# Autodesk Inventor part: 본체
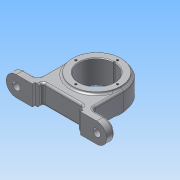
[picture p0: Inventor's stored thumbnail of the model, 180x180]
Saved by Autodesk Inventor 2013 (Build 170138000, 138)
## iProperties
Created: 2019-05
Part Number: 본체
Material: 알루미늄 6061
Document SubType Name: Modeling
Designer: Gpr
Density: 2.71 g/cm^3
Mass: 456.571 g
Surface Area: 322.88 cm^2
Volume: 168.476 cm^3
Author: Gpr
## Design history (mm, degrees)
sketch "스케치1"
  geometry: L1 (-30, 0)-(-30, -6); L2 (-30, -6)-(-36, -6); L3 (-36, -6)-(-36, -10); L4 (-36, -10)-(-75, -10); L5 (-75, -10)-(-75, 2); L6 (-30, 0)-(0, 0); L7 (0, 10.162)-(0, 0); L8 (30, -6)-(36, -6); L9 (30, 0)-(30, -6); L10 (30, 0)-(0, 0); L11 (75, -10)-(75, 2); L12 (36, -10)-(75, -10); L13 (36, -6)-(36, -10); L14 (-40, 50)-(-40, 2); L15 (40, 50)-(40, 2); L16 (-75, 2)-(-40, 2); L17 (40, 2)-(75, 2); L18 (-40, 50)-(40, 50); A1 r 40 centre (0, 50) between (-40, 50) and (40, 50); 2 further points
  constraints: 36 end point, 8 symmetric about line, 5 horizontal, 5 vertical, 3 coincident, 2 point on circle, 1 centre point, 1 point on line, 1 tangent, 1 vertical alignment
  dimensions: "d4" = 10 distance between parallel lines of L6 L4; "d6" = 30 distance from line of point (0, 0) L1; "d7" = 4 distance between parallel lines of L4 L2; "d8" = 75 distance from line of point (0, 0) L5; "d9" = 72 distance between parallel lines of L13 L3; "d11" = 80 diameter of A1; "d12" = 60 distance from line of L4 A1.centre; "d13" = 12 distance between parallel lines of L4 L16
extrude "돌출1" new body sketch "스케치1" stored distance "d14" = 30; taper "d15" = 0 deg
sketch "스케치2"
  geometry: L1 (-30, 0)-(-30, -6) reference; L2 (-30, -6)-(-36, -6) reference; L3 (-36, -6)-(-36, -10) reference; L4 (-36, -10)-(-75, -10) reference; L5 (-75, -10)-(-75, 2) reference; L6 (-75, 2)-(-40, 2) reference; L7 (-40, 2)-(-40, 50) reference; L8 (40, 50)-(40, 2) reference; L9 (40, 2)-(75, 2) reference; L10 (75, 2)-(75, -10) reference; L11 (75, -10)-(36, -10) reference; L12 (36, -10)-(36, -6) reference; L13 (36, -6)-(30, -6) reference; L14 (30, -6)-(30, 0) reference; L15 (30, 0)-(-30, 0) reference; C1 r 36 at (0, 50); A1 r 40 centre (0, 50) between (40, 50) and (-40, 50) reference; 1 further point
  constraints: 1 centre point, 1 coincident
  dimensions: "d16" = 72 diameter of C1
extrude "돌출2" join sketch "스케치2" stored distance "d17" = 36; taper "d18" = 0 deg
sketch "스케치3"
  geometry: C1 r 36 at (0, 0) reference; C2 r 26 at (0, 0); 1 further point
  constraints: 1 centre point, 1 coincident
  dimensions: "d19" = 52 diameter of C2
extrude "돌출3" cut sketch "스케치3" stored distance "d21" = 36; taper "d22" = 0 deg
sketch "스케치4" dims "d23" = 62
  geometry: C1 r 26 at (0, 0) reference; C2 r 36 at (0, 0) reference; 3 further points
  constraints: 2 vertical alignment, 1 coincident, 2 other
hole "구멍1" sketch "스케치4" at (0, 31) diameter "d24" = 3.242; stored, may be unused: countersink angle "d28" = 90 deg, drill point angle "d30" = 118 deg; dims "d25" = 6, "d26" = 4, "d27" = 2, "d29" = 8
sketch "스케치5"
  geometry: L1 (0, 0)-(39, 0) reference; L2 (111, 0)-(150, 0) reference; C1 r 9 at (15, 15); C2 r 9 at (135, 15); 1 further point
  constraints: 2 centre point
  dimensions: "d34" = 18 diameter of C1; "d36" = 60 distance of point (75, 15) C1.centre; "d37" = 18 diameter of C2; "d38" = 60 distance of C2.centre point (75, 15); "d39" = 15 distance from line of L1 C1.centre; "d40" = 15 distance from line of C2.centre L2
extrude "돌출4" join sketch "스케치5" distance "d41" = 3; taper "d42" = 0 deg
sketch "스케치6"
  geometry: L1 (20, 15)-(100, 15) reference; L2 (100, 15)-(100, -15) reference; L3 (100, -15)-(20, -15) reference; L4 (20, -15)-(20, 15) reference; C1 r 9 at (0, 0) reference; C2 r 9 at (120, 0) reference; C3 r 5.5 at (0, 0); C4 r 5.5 at (120, 0); 1 further point
  constraints: 2 centre point, 2 coincident
  dimensions: "d43" = 11 diameter of C3; "d44" = 11 diameter of C4
extrude "돌출5" cut sketch "스케치6" stored distance "d45" = 3; taper "d46" = 0 deg
node "작업 평면1"
sketch "스케치7"
  geometry: 2 further points
  constraints: 2 coincident
hole "구멍2" sketch "스케치7" at (0, 0) diameter "d47" = 4.917; stored, may be unused: countersink angle "d51" = 90 deg, drill point angle "d53" = 118 deg; dims "d48" = 8, "d49" = 7, "d50" = 1, "d52" = 10
sketch "스케치8"
  geometry: C1 r 1.621 at (-31, 0) reference; C2 r 1.621 at (0, -31) reference; C3 r 1.621 at (31, 0) reference; C4 r 1.621 at (0, 31) reference; C5 r 36 at (0, 0) reference; C6 r 1.5 at (0, 26); 2 further points
  constraints: 2 vertical alignment, 1 centre point, 1 other
  dimensions: "d54" = 3 diameter of C6
extrude "돌출6" cut sketch "스케치8" stored distance "d56" = 3; taper "d57" = 0 deg
fillet "모깎기1" dims "d58" = 3
fillet "모깎기2" dims "d59" = 3
fillet "모깎기3" dims "d60" = 3
fillet "모깎기4" dims "d61" = 15
fillet "모깎기5" dims "d62" = 6
fillet "모깎기6" dims "d63" = 3
fillet "모깎기7" dims "d64" = 3
fillet "모깎기8" dims "d65" = 3
fillet "모깎기9" dims "d66" = 3
node "작업 평면2"
sketch "스케치9"
  geometry: 2 further points
  constraints: 1 vertical alignment, 1 other
  dimensions: "d68" = 7 distance of point (0, 7) point (0, 0)
feature "엠보싱1" sketch "스케치9" dims "d69" = 1, "d70" = 0
sketch "스케치10"
  geometry: C1 r 1 at (0, 0); 1 further point
  constraints: 1 centre point, 1 coincident
  dimensions: "d71" = 2 diameter of C1
extrude "돌출7" cut sketch "스케치10" stored distance "d73" = 3; taper "d74" = 0 deg
chamfer "모따기1" distance "d75" = 1; stored, may be unused: second distance "d76" = 2, angle "d77" = 45 deg
chamfer "모따기2" distance "d78" = 1; stored, may be unused: second distance "d79" = 2, angle "d80" = 45 deg
fillet "모깎기10" dims "d81" = 3
node "솔리드1"
pattern_circular "원형 패턴1" dims angle "d32" = 360 deg
mirror "대칭1"
node "절단 모서리 투영1"
node "절단 모서리 투영2"
node "절단 모서리 투영3"
node "절단 모서리 투영4"
node "절단 모서리 투영5"
other parameters: "d10" = 12, "d67" = 98
